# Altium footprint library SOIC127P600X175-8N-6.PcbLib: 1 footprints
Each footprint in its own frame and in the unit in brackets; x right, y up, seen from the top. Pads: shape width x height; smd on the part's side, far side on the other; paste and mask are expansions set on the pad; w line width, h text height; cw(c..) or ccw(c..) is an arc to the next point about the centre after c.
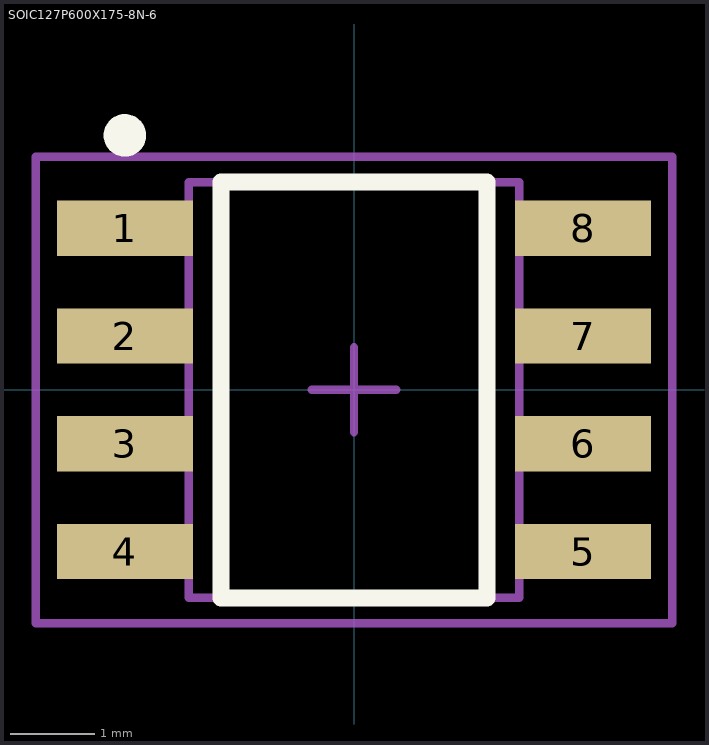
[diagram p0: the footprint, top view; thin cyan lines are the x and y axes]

## SOIC127P600X175-8N-6 [mm] "SOIC,1.27mm pitch;8 pin,3.90mm W X 4.90mm L X 1.75mm H body"
height 1.75
pads (8):
  rect 1.6x0.65 smd paste+0 mask+0: 1(-2.7,1.905) 2(-2.7,0.635) 3(-2.7,-0.635) 4(-2.7,-1.905) 5(2.7,-1.905) 6(2.7,-0.635) 7(2.7,0.635) 8(2.7,1.905)
Top Overlay:
  circle w0.25: c-2.7,3 r0.125
  lines w0.2: -1.57,-2.45 -1.57,2.45 1.57,2.45 1.57,-2.45 -1.57,-2.45
Mechanical 3:
  text ".DESIGNATOR" at 0,0 h1.2
Mechanical 13:
  lines w0.1: -1.95,-2.45 -1.95,2.45 1.95,2.45 1.95,-2.45 -1.95,-2.45
Mechanical 15:
  lines w0.1: -0.5,0 0.5,0 ; 0,-0.5 0,0.5 ; -3.75,-2.75 -3.75,2.75 3.75,2.75 3.75,-2.75 -3.75,-2.75
3D body: height 1.76, standoff 0, extent -3,-2.5 3,2.5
